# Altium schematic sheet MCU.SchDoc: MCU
size A3; DocumentNumber: MB1165; Revision: C.1; SheetNumber: 2; SheetTotal: 17; Project: STM32469I-EVAL
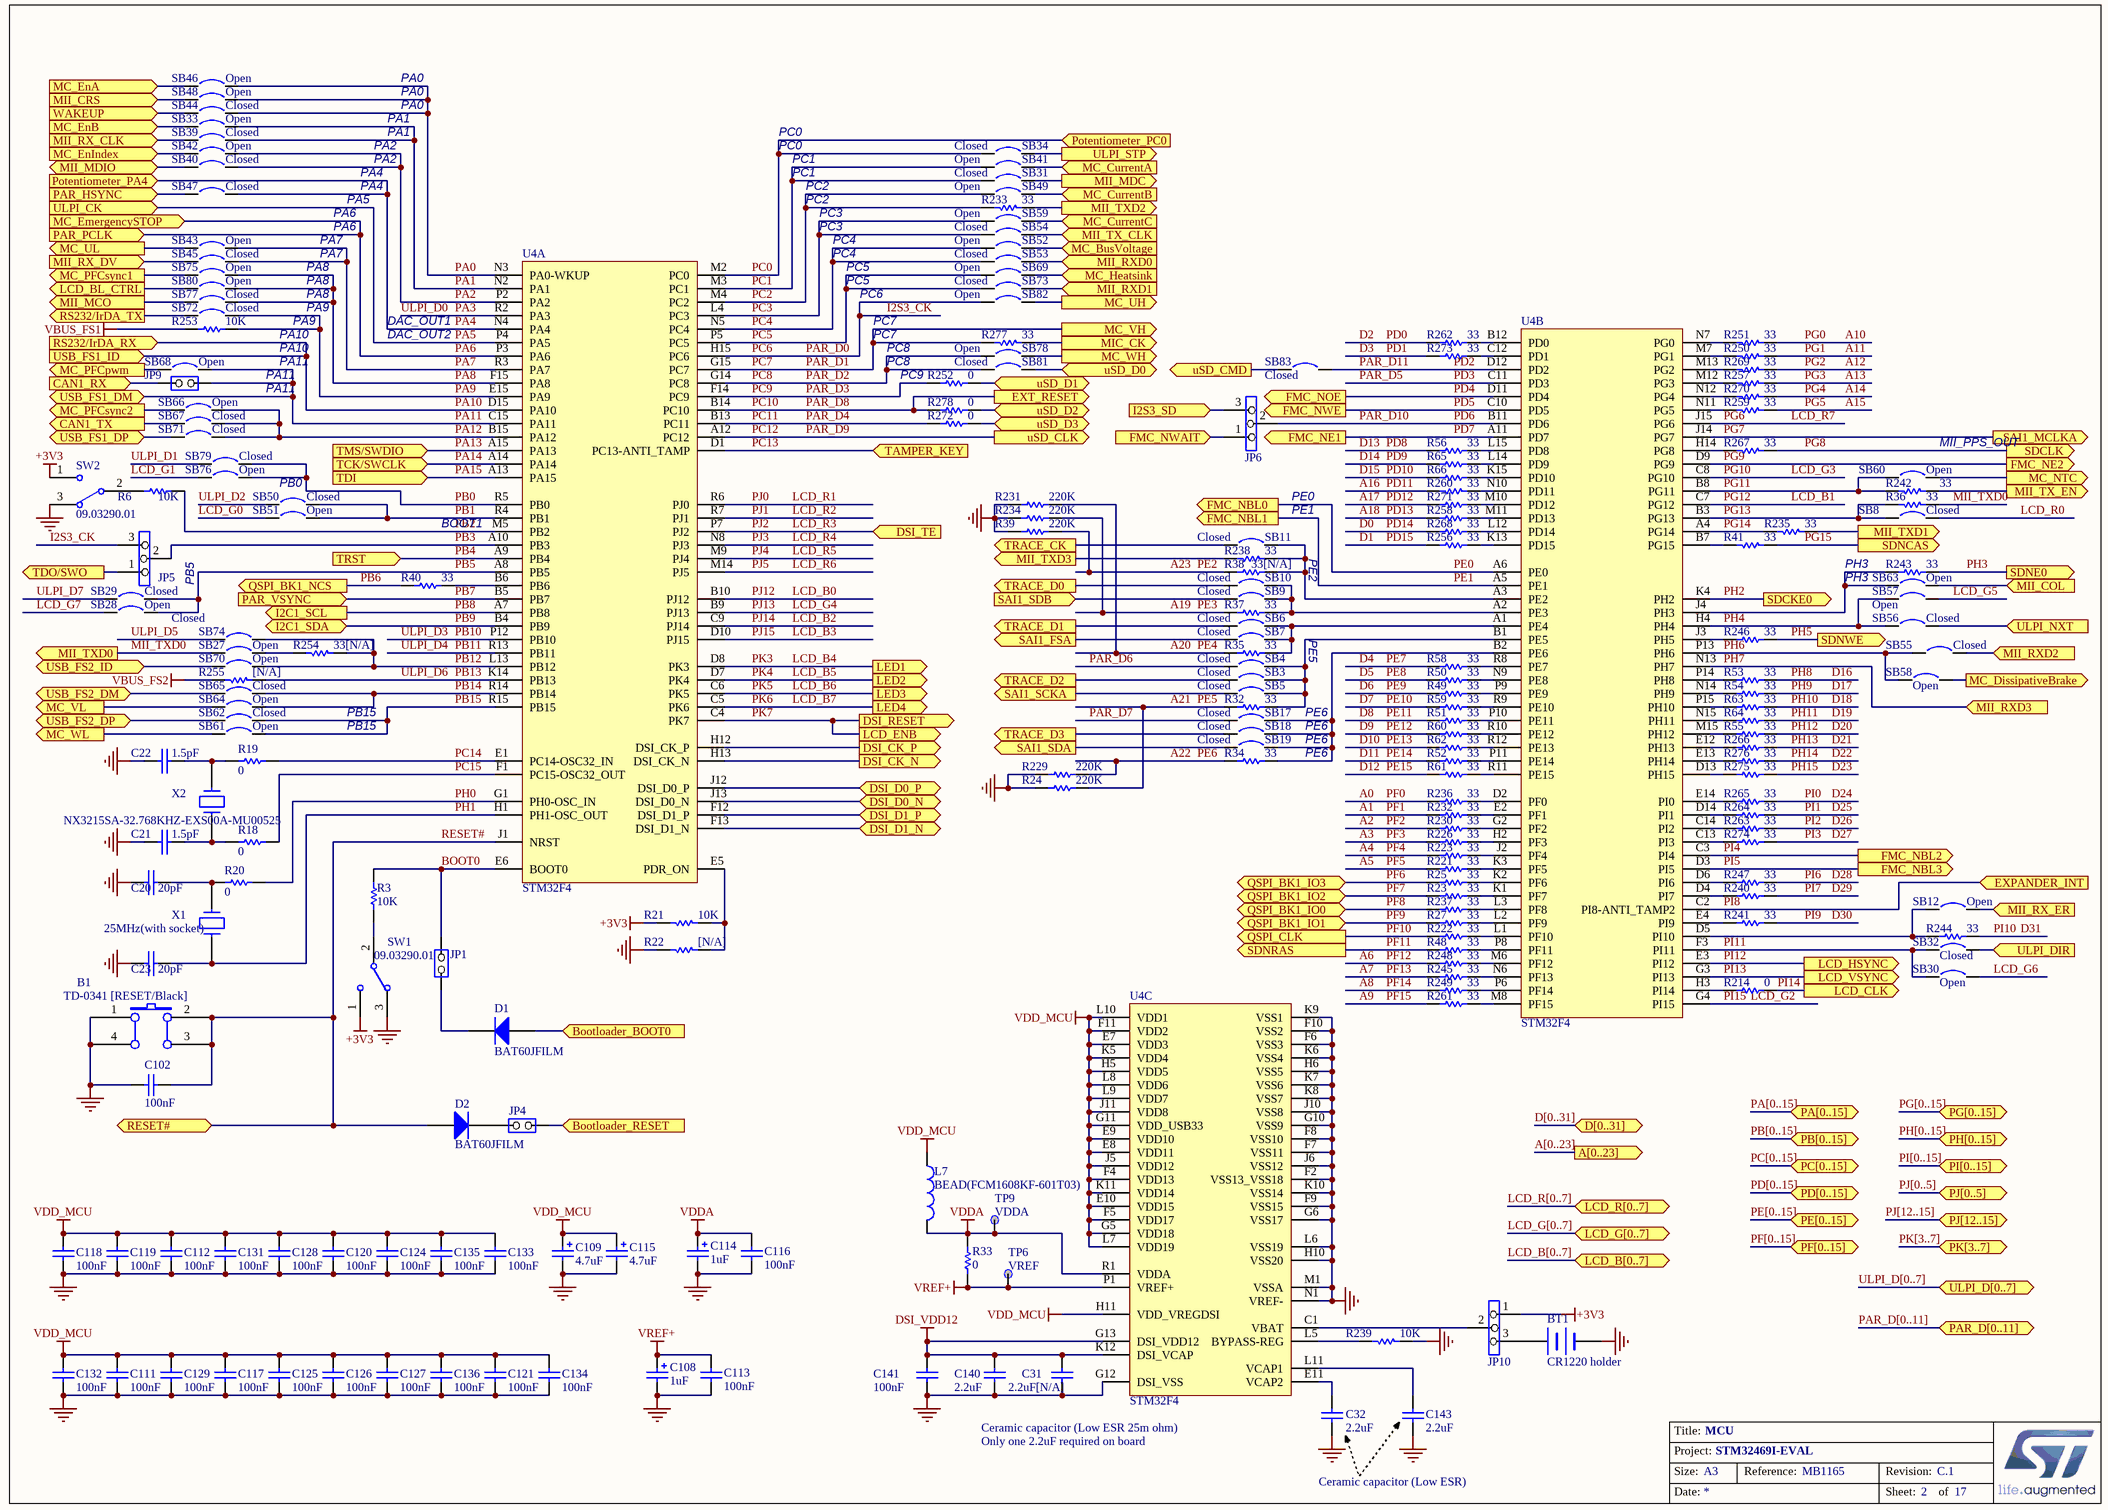
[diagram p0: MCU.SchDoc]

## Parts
B1  TD-0341 [RESET/Black]  [PB10]
BT1  CR1220 holder  [BAT_2SM_CR1220]
C20  20pF  [0603C]
C21  1.5pF  [0603C]
C22  1.5pF  [0603C]
C23  20pF  [0603C]
C31  2.2uF[N/A]  [1206C]
C32  2.2uF  [1206C]
C102  100nF  [0603C]
C108  1uF  [TAN-A]
C109  4.7uF  [TAN-A]
C111  100nF  [0402C]
C112  100nF  [0402C]
C113  100nF  [0402C]
C114  1uF  [TAN-A]
C115  4.7uF  [TAN-A]
C116  100nF  [0402C]
C117  100nF  [0402C]
C118  100nF  [0402C]
C119  100nF  [0402C]
C120  100nF  [0402C]
C121  100nF  [0402C]
C124  100nF  [0402C]
C125  100nF  [0402C]
C126  100nF  [0402C]
C127  100nF  [0402C]
C128  100nF  [0402C]
C129  100nF  [0402C]
C131  100nF  [0402C]
C132  100nF  [0402C]
C133  100nF  [0402C]
C134  100nF  [0402C]
C135  100nF  [0402C]
C136  100nF  [0402C]
C140  2.2uF  [0402C]
C141  100nF  [0402C]
C143  2.2uF  [1206C]
D1  BAT60JFILM  [SOD-323]
D2  BAT60JFILM  [SOD-323]
JP1  (no value)  [SIP2]
JP4  (no value)  [SIP2]
JP5  (no value)  [SIP3]
JP6  (no value)  [SIP3]
JP9  (no value)  [SIP2]
JP10  (no value)  [SIP3]
L7  BEAD(FCM1608KF-601T03)  [0603L]
R3  10K  [0603R]
R6  10K  [0603R]
R18  0  [0603R]
R19  0  [0603R]
R20  0  [0603R]
R21  10K  [0603R]
R22  [N/A]  [0603R]
R23  33  [0402R]
R24  220K  [0603R]
R25  33  [0402R]
R27  33  [0402R]
R32  33  [0402R]
R33  0  [0603R]
R34  33  [0402R]
R35  33  [0402R]
R36  33  [0603R]
R37  33  [0402R]
R38  33[N/A]  [0402R]
R39  220K  [0603R]
R40  33  [0402R]
R41  33  [0402R]
R48  33  [0402R]
R49  33  [0402R]
R50  33  [0402R]
R51  33  [0402R]
R52  33  [0402R]
R53  33  [0402R]
R54  33  [0402R]
R55  33  [0402R]
R56  33  [0402R]
R58  33  [0402R]
R59  33  [0402R]
R60  33  [0402R]
R61  33  [0402R]
R62  33  [0402R]
R63  33  [0402R]
R64  33  [0402R]
R65  33  [0402R]
R66  33  [0402R]
R214  0  [0603R]
R221  33  [0402R]
R222  33  [0402R]
R223  33  [0402R]
R226  33  [0402R]
R229  220K  [0603R]
R230  33  [0402R]
R231  220K  [0603R]
R232  33  [0402R]
R233  33  [0603R]
R234  220K  [0603R]
R235  33  [0603R]
R236  33  [0402R]
R237  33  [0402R]
R238  33  [0603R]
R239  10K  [0603R]
R240  33  [0402R]
R241  33  [0402R]
R242  33  [0603R]
R243  33  [0402R]
R244  33  [0402R]
R245  33  [0402R]
R246  33  [0402R]
R247  33  [0402R]
R248  33  [0402R]
R249  33  [0402R]
R250  33  [0402R]
R251  33  [0402R]
R252  0  [0603R]
R253  10K  [0603R]
R254  33[N/A]  [0603R]
R255  [N/A]  [0603R]
R256  33  [0402R]
R257  33  [0402R]
R258  33  [0402R]
R259  33  [0402R]
R260  33  [0402R]
R261  33  [0402R]
R262  33  [0402R]
R263  33  [0402R]
R264  33  [0402R]
R265  33  [0402R]
R266  33  [0402R]
R267  33  [0402R]
R268  33  [0402R]
R269  33  [0402R]
R270  33  [0402R]
R271  33  [0402R]
R272  0  [0603R]
R273  33  [0402R]
R274  33  [0402R]
R275  33  [0402R]
R276  33  [0402R]
R277  33  [0603R]
R278  0  [0603R]
SB3  Closed  [SB_0603]
SB4  Closed  [SB_0603]
SB5  Closed  [SB_0603]
SB6  Closed  [SB_0603]
SB7  Closed  [SB_0603]
SB8  Closed  [SB_0603]
SB9  Closed  [SB_0603]
SB10  Closed  [SB_0603]
SB11  Closed  [SB_0603]
SB12  Open  [SB_0603]
SB17  Closed  [SB_0603]
SB18  Closed  [SB_0603]
SB19  Closed  [SB_0603]
SB27  Open  [SB_0603]
SB28  Open  [SB_0603]
SB29  Closed  [SB_0603]
SB30  Open  [SB_0603]
SB31  Closed  [SB_0603]
SB32  Closed  [SB_0603]
SB33  Open  [SB_0603]
SB34  Closed  [SB_0603]
SB39  Closed  [SB_0603]
SB40  Closed  [SB_0603]
SB41  Open  [SB_0603]
SB42  Open  [SB_0603]
SB43  Open  [SB_0603]
SB44  Closed  [SB_0603]
SB45  Closed  [SB_0603]
SB46  Open  [SB_0603]
SB47  Closed  [SB_0603]
SB48  Open  [SB_0603]
SB49  Open  [SB_0603]
SB50  Closed  [SB_0603]
SB51  Open  [SB_0603]
SB52  Open  [SB_0603]
SB53  Closed  [SB_0603]
SB54  Closed  [SB_0603]
SB55  Closed  [SB_0603]
SB56  Closed  [SB_0603]
SB57  Open  [SB_0603]
SB58  Open  [SB_0603]
SB59  Open  [SB_0603]
SB60  Open  [SB_0603]
SB61  Open  [SB_0603]
SB62  Closed  [SB_0603]
SB63  Open  [SB_0603]
SB64  Open  [SB_0603]
SB65  Closed  [SB_0603]
SB66  Open  [SB_0603]
SB67  Closed  [SB_0603]
SB68  Open  [SB_0603]
SB69  Open  [SB_0603]
SB70  Open  [SB_0603]
SB71  Closed  [SB_0603]
SB72  Closed  [SB_0603]
SB73  Closed  [SB_0603]
SB74  Closed  [SB_0603]
SB75  Open  [SB_0603]
SB76  Open  [SB_0603]
SB77  Closed  [SB_0603]
SB78  Open  [SB_0603]
SB79  Closed  [SB_0603]
SB80  Open  [SB_0603]
SB81  Closed  [SB_0603]
SB82  Open  [SB_0603]
SB83  Closed  [SB_0603]
SW1  09.03290.01  [SW1_3TH_2R54_10X2R5]
SW2  09.03290.01  [SW1_3TH_2R54_10X2R5]
TP6  VREF  [TP]
TP9  VDDA  [TP]
U4  STM32F4  [BGA216_0R8_13X13_SKT]  (parts A,B,C of 3)
X1  25MHz(with socket)  [XTAL_socket]
X2  NX3215SA-32.768KHZ-EXS00A-MU00525  [XTAL_2SM_3R2X1R5]

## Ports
A[0..23] (out), Bootloader_BOOT0 (in), Bootloader_RESET (in), CAN1_RX (in), CAN1_TX (out), D[0..31] (bidir), DSI_CK_N (out), DSI_CK_P (out), DSI_D0_N (bidir), DSI_D0_P (bidir), DSI_D1_N (bidir), DSI_D1_P (bidir), DSI_RESET (out), DSI_TE (in), EXPANDER_INT (in), EXT_RESET (out), FMC_NBL0 (out), FMC_NBL1 (out), FMC_NBL2 (out), FMC_NBL3 (out), FMC_NE1 (out), FMC_NE2 (out), FMC_NOE (out), FMC_NWAIT (in), FMC_NWE (out), I2C1_SCL (out), I2C1_SDA (bidir), I2S3_SD (in), LCD_B[0..7] (bidir), LCD_BL_CTRL (out), LCD_CLK (out), LCD_ENB (out), LCD_G[0..7] (bidir), LCD_HSYNC (out), LCD_R[0..7] (bidir), LCD_VSYNC (out), LED1 (out), LED2 (out), LED3 (out), LED4 (out), MC_BusVoltage (in), MC_CurrentA (in), MC_CurrentB (in), MC_CurrentC (in), MC_DissipativeBrake (out), MC_EmergencySTOP (in), MC_EnA (in), MC_EnB (in), MC_EnIndex (in), MC_Heatsink (in), MC_NTC (out), MC_PFCpwm (out), MC_PFCsync1 (out), MC_PFCsync2 (out), MC_UH (out), MC_UL (out), MC_VH (out), MC_VL (out), MC_WH (out), MC_WL (out), MIC_CK (out), MII_COL (in), MII_CRS (in), MII_MCO (out), MII_MDC (out), MII_MDIO (bidir), MII_RX_CLK (in), MII_RX_DV (in), MII_RX_ER (in), MII_RXD0 (in), MII_RXD1 (in), MII_RXD2 (in), MII_RXD3 (in), MII_TX_CLK (in), MII_TX_EN (out), MII_TXD0 (out), MII_TXD1 (out), MII_TXD2 (out), MII_TXD3 (out), PA[0..15] (bidir), PAR_D[0..11] (bidir), PAR_HSYNC (in), PAR_PCLK (in), PAR_VSYNC (in), PB[0..15] (bidir), PC[0..15] (bidir), PD[0..15] (bidir), PE[0..15] (bidir), PF[0..15] (bidir), PG[0..15] (bidir), PH[0..15] (bidir), PI[0..15] (bidir), PJ[0..5] (bidir), PJ[12..15] (bidir), PK[3..7] (bidir), Potentiometer_PA4 (in), Potentiometer_PC0 (in), QSPI_BK1_IO0 (bidir), QSPI_BK1_IO1 (bidir), QSPI_BK1_IO2 (bidir), QSPI_BK1_IO3 (bidir), QSPI_BK1_NCS (out), QSPI_CLK (out), RESET# (bidir), RS232/IrDA_RX (in), RS232/IrDA_TX (out), SAI1_FSA (out), SAI1_MCLKA (out), SAI1_SCKA (out), SAI1_SDA (out), SAI1_SDB (in), SDCKE0 (out), SDCLK (out), SDNCAS (out), SDNE0 (out), SDNRAS (out), SDNWE (out), TAMPER_KEY (in), TCK/SWCLK (in), TDI (in), TDO/SWO (out), TMS/SWDIO (in), TRACE_CK (out), TRACE_D0 (out), TRACE_D1 (out), TRACE_D2 (out), TRACE_D3 (out), TRST (in), ULPI_CK (in), ULPI_D[0..7] (bidir), ULPI_DIR (in), ULPI_NXT (in), ULPI_STP (out), USB_FS1_DM (bidir), USB_FS1_DP (bidir), USB_FS1_ID (in), USB_FS2_DM (bidir), USB_FS2_DP (bidir), USB_FS2_ID (bidir), uSD_CLK (out), uSD_CMD (out), uSD_D0 (bidir), uSD_D1 (bidir), uSD_D2 (bidir), uSD_D3 (bidir), WAKEUP (in)

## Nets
+3V3: JP10.1 R21.2 SW1.1 SW2.1
DSI_VDD12: C31.1 C140.1 C141.1 U4.G13(DSI_VDD12) U4.K12(DSI_VCAP)
GND: B1.1(A0) B1.4(A1) BT1.2(-) C20.2 C21.2 C22.2 C23.2 C31.2 C32.2 C102.1 C108.2 C109.2 C111.2 C112.2 C113.1 C114.2 C115.2 C116.1 C117.2 C118.2 C119.2 C120.2 C121.2 C124.2 C125.2 C126.2 C127.2 C128.2 C129.2 C131.2 C132.2 C133.2 C134.2 C135.2 C136.2 C140.2 C141.2 C143.2 R22.2 R24.1 R39.1 R229.1 R231.1 R234.1 R239.1 SW1.3 SW2.3 U4.F2(VSS13_VSS18) U4.F6(VSS3) U4.F7(VSS11) U4.F8(VSS10) U4.F9(VSS15) U4.F10(VSS2) U4.G6(VSS17) U4.G10(VSS9) U4.G12(DSI_VSS) U4.H6(VSS5) U4.H10(VSS20) U4.J6(VSS12) U4.J10(VSS8) U4.K6(VSS4) U4.K7(VSS6) U4.K8(VSS7) U4.K9(VSS1) U4.K10(VSS14) U4.L6(VSS19) U4.M1(VSSA) U4.N1(VREF-)
VBUS_FS1: R253.2
VBUS_FS2: R255.1
VDD_MCU: C109.1 C111.1 C112.1 C115.1 C117.1 C118.1 C119.1 C120.1 C121.1 C124.1 C125.1 C126.1 C127.1 C128.1 C129.1 C131.1 C132.1 C133.1 C134.1 C135.1 C136.1 L7.1 U4.E7(VDD3) U4.E8(VDD11) U4.E9(VDD10) U4.E10(VDD15) U4.F4(VDD13) U4.F5(VDD17) U4.F11(VDD2) U4.G5(VDD18) U4.G11(VDD_USB33) U4.H5(VDD5) U4.H11(VDD_VREGDSI) U4.J5(VDD12) U4.J11(VDD8) U4.K5(VDD4) U4.K11(VDD14) U4.L7(VDD19) U4.L8(VDD6) U4.L9(VDD7) U4.L10(VDD1)
VDDA: C114.1 C116.2 L7.2 R33.1 TP9.1 U4.R1(VDDA)
VREF+: C108.1 C113.2 R33.2 TP6.1 U4.P1(VREF+)
A0: R236.2  [also labelled PF0]
A1: R232.2  [also labelled PF1]
A2: R230.2  [also labelled PF2]
A3: R226.2  [also labelled PF3]
A4: R223.2  [also labelled PF4]
A5: R221.2  [also labelled PF5]
A6: R248.2  [also labelled PF12]
A7: R245.2  [also labelled PF13]
A8: R249.2  [also labelled PF14]
A9: R261.2  [also labelled PF15]
A10: R251.2  [also labelled PG0]
A11: R250.2  [also labelled PG1]
A12: R269.2  [also labelled PG2]
A13: R257.2  [also labelled PG3]
A14: R270.2  [also labelled PG4]
A15: R259.2  [also labelled PG5]
A16: R260.1  [also labelled PD11]
A17: R271.2  [also labelled PD12]
A18: R258.2  [also labelled PD13]
A19: R37.2 R234.2  [also labelled PE3]
A20: R35.2 R231.2  [also labelled PE4]
A21: R24.2 R32.2  [also labelled PE5]
A22: R34.2 R229.2  [also labelled PE6]
A23: R38.2 R39.2  [also labelled PE2]
BOOT0: JP1.2(NO) R3.1 U4.E6(BOOT0)
Bootloader_BOOT0: D1.1(A) ; port Bootloader_BOOT0
Bootloader_RESET: JP4.2(NO) ; port Bootloader_RESET
CAN1_RX: JP9.2(NO) ; port CAN1_RX
CAN1_TX: SB67.1 ; port CAN1_TX
D0: R268.2  [also labelled PD14]
D1: R256.2  [also labelled PD15]
D2: R262.2  [also labelled PD0]
D3: R273.2  [also labelled PD1]
D4: R58.2  [also labelled PE7]
D5: R50.2  [also labelled PE8]
D6: R49.2  [also labelled PE9]
D7: R59.2  [also labelled PE10]
D8: R51.2  [also labelled PE11]
D9: R60.2  [also labelled PE12]
D10: R62.2  [also labelled PE13]
D11: R52.2  [also labelled PE14]
D12: R61.2  [also labelled PE15]
D13: R56.2  [also labelled PD8]
D14: R65.2  [also labelled PD9]
D15: R66.2  [also labelled PD10]
D16: R53.1  [also labelled PH8]
D17: R54.1  [also labelled PH9]
D18: R63.1  [also labelled PH10]
D19: R64.1  [also labelled PH11]
D20: R55.1  [also labelled PH12]
D21: R266.1  [also labelled PH13]
D22: R276.1  [also labelled PH14]
D23: R275.1  [also labelled PH15]
D24: R265.1  [also labelled PI0]
D25: R264.1  [also labelled PI1]
D26: R263.1  [also labelled PI2]
D27: R274.1  [also labelled PI3]
D28: R247.1  [also labelled PI6]
D29: R240.1  [also labelled PI7]
D30: R241.1  [also labelled PI9]
D31: R244.1  [also labelled PI10]
DSI_CK_N: U4.H13(DSI_CK_N) ; port DSI_CK_N
DSI_CK_P: U4.H12(DSI_CK_P) ; port DSI_CK_P
DSI_D0_N: U4.J13(DSI_D0_N) ; port DSI_D0_N
DSI_D0_P: U4.J12(DSI_D0_P) ; port DSI_D0_P
DSI_D1_N: U4.F13(DSI_D1_N) ; port DSI_D1_N
DSI_D1_P: U4.F12(DSI_D1_P) ; port DSI_D1_P
FMC_NWAIT: JP6.1 ; port FMC_NWAIT
I2S3_CK: JP5.3 SB82.1 U4.H15(PC6)  [also labelled PAR_D0, PC6]
I2S3_SD: JP6.3 ; port I2S3_SD
LCD_B0: U4.B10(PJ12)  [also labelled PJ12]
LCD_B1: U4.C7(PG12)  [also labelled PG12]
LCD_B2: U4.C9(PJ14)  [also labelled PJ14]
LCD_B3: U4.D10(PJ15)  [also labelled PJ15]
LCD_B4: U4.D8(PK3) ; port LED1  [also labelled PK3]
LCD_B5: U4.D7(PK4) ; port LED2  [also labelled PK4]
LCD_B6: U4.C6(PK5) ; port LED3  [also labelled PK5]
LCD_B7: U4.C5(PK6) ; port LED4  [also labelled PK6]
LCD_BL_CTRL: SB80.1 ; port LCD_BL_CTRL
LCD_G0: SB51.1
LCD_G1: SB76.1
LCD_G2: U4.G4(PI15)  [also labelled PI15]
LCD_G3: U4.C8(PG10)  [also labelled PG10]
LCD_G4: U4.B9(PJ13)  [also labelled PJ13]
LCD_G5: SB57.2
LCD_G6: SB30.2
LCD_G7: SB28.1
LCD_R0: SB8.2
LCD_R1: U4.R6(PJ0)  [also labelled PJ0]
LCD_R2: U4.R7(PJ1)  [also labelled PJ1]
LCD_R3: U4.P7(PJ2) ; port DSI_TE  [also labelled PJ2]
LCD_R4: U4.N8(PJ3)  [also labelled PJ3]
LCD_R5: U4.M9(PJ4)  [also labelled PJ4]
LCD_R6: U4.M14(PJ5)  [also labelled PJ5]
LCD_R7: U4.J15(PG6)  [also labelled PG6]
MC_BusVoltage: SB52.2 ; port MC_BusVoltage
MC_CurrentA: SB41.2 ; port MC_CurrentA
MC_CurrentB: SB49.2 ; port MC_CurrentB
MC_CurrentC: SB59.2 ; port MC_CurrentC
MC_DissipativeBrake: SB58.2 ; port MC_DissipativeBrake
MC_EnA: SB46.1 ; port MC_EnA
MC_EnB: SB33.1 ; port MC_EnB
MC_EnIndex: SB42.1 ; port MC_EnIndex
MC_Heatsink: SB69.2 ; port MC_Heatsink
MC_NTC: SB60.2 ; port MC_NTC
MC_PFCpwm: SB68.1 ; port MC_PFCpwm
MC_PFCsync1: SB75.1 ; port MC_PFCsync1
MC_PFCsync2: SB66.1 ; port MC_PFCsync2
MC_UH: SB82.2 ; port MC_UH
MC_UL: SB43.1 ; port MC_UL
MC_VL: SB64.1 ; port MC_VL
MC_WH: SB78.2 ; port MC_WH
MC_WL: SB61.1 ; port MC_WL
MIC_CK: R277.2 ; port MIC_CK
MII_COL: SB63.2 ; port MII_COL
MII_CRS: SB48.1 ; port MII_CRS
MII_MCO: SB77.1 ; port MII_MCO
MII_MDC: SB31.2 ; port MII_MDC
MII_MDIO: SB40.1 ; port MII_MDIO
MII_RX_CLK: SB39.1 ; port MII_RX_CLK
MII_RX_DV: SB45.1 ; port MII_RX_DV
MII_RX_ER: SB12.2 ; port MII_RX_ER
MII_RXD0: SB53.2 ; port MII_RXD0
MII_RXD1: SB73.2 ; port MII_RXD1
MII_RXD2: SB55.2 ; port MII_RXD2
MII_TX_CLK: SB54.2 ; port MII_TX_CLK
MII_TX_EN: R242.2 ; port MII_TX_EN
MII_TXD0: R36.2 SB27.1 ; port MII_TXD0
MII_TXD1: R235.2 ; port MII_TXD1
MII_TXD2: R233.2 ; port MII_TXD2
MII_TXD3: R238.1 ; port MII_TXD3
PA0: SB44.2 SB46.2 SB48.2 U4.N3(PA0-WKUP)
PA1: SB33.2 SB39.2 U4.N2(PA1)
PA2: SB40.2 SB42.2 U4.P2(PA2)
PA3: U4.R2(PA3)  [also labelled ULPI_D0]
PA4: SB47.2 U4.N4(PA4) ; port Potentiometer_PA4
PA5: U4.P4(PA5) ; port ULPI_CK
PA6: U4.P3(PA6) ; port MC_EmergencySTOP, port PAR_PCLK
PA7: SB43.2 SB45.2 U4.R3(PA7)
PA8: SB75.2 SB77.2 SB80.2 U4.F15(PA8)
PA9: R253.1 SB72.2 U4.E15(PA9)
PA10: U4.D15(PA10) ; port RS232/IrDA_RX, port USB_FS1_ID
PA11: JP9.1(COMMON) SB68.2 U4.C15(PA11) ; port USB_FS1_DM
PA12: SB66.2 SB67.2 SB71.2 U4.B15(PA12)
PA13: U4.A15(PA13) ; port TMS/SWDIO
PA14: U4.A14(PA14) ; port TCK/SWCLK
PA15: U4.A13(PA15) ; port TDI
PAR_D1: R277.1 U4.G15(PC7) ; port MC_VH  [also labelled PC7]
PAR_D2: SB78.1 SB81.1 U4.G14(PC8)  [also labelled PC8]
PAR_D3: R252.2 U4.F14(PC9)  [also labelled PC9]
PAR_D4: R272.2 U4.B13(PC11)  [also labelled PC11]
PAR_D5: U4.C11(PD3)  [also labelled PD3]
PAR_D6: SB4.1
PAR_D7: SB17.1
PAR_D8: R278.2 U4.B14(PC10) ; port EXT_RESET  [also labelled PC10]
PAR_D9: U4.A12(PC12) ; port uSD_CLK  [also labelled PC12]
PAR_D10: JP6.2 U4.B11(PD6)  [also labelled PD6]
PAR_D11: SB83.2 U4.D12(PD2)  [also labelled PD2]
PAR_HSYNC: SB47.1 ; port PAR_HSYNC
PB0: SB76.2 SB79.2 U4.R5(PB0)
PB1: SB50.2 SB51.2 U4.R4(PB1)
PB2: R6.2 U4.M5(PB2)
PB3: JP5.2 U4.A10(PB3)
PB4: U4.A9(PB4) ; port TRST
PB5: SB28.2 SB29.2 U4.A8(PB5)
PB6: R40.2 ; port QSPI_BK1_NCS
PB7: U4.B5(PB7) ; port PAR_VSYNC
PB8: U4.A7(PB8) ; port I2C1_SCL
PB9: U4.B4(PB9) ; port I2C1_SDA
PB10: U4.P12(PB10)  [also labelled ULPI_D3]
PB11: U4.R13(PB11)  [also labelled ULPI_D4]
PB12: R254.2 SB70.2 SB74.2 U4.L13(PB12)
PB13: R255.2 U4.K14(PB13)  [also labelled ULPI_D6]
PB14: SB64.2 SB65.2 U4.R14(PB14)
PB15: SB61.2 SB62.2 U4.R15(PB15)
PC0: SB34.1 U4.M2(PC0) ; port Potentiometer_PC0
PC1: SB31.1 SB41.1 U4.M3(PC1)
PC2: R233.1 SB49.1 U4.M4(PC2)
PC3: SB54.1 SB59.1 U4.L4(PC3)
PC4: SB52.1 SB53.1 U4.N5(PC4)
PC5: SB69.1 SB73.1 U4.P5(PC5)
PC13: U4.D1(PC13-ANTI_TAMP) ; port TAMPER_KEY
PC14: R19.2 U4.E1(PC14-OSC32_IN)
PC15: R18.2 U4.F1(PC15-OSC32_OUT)
PD4: U4.D11(PD4) ; port FMC_NOE
PD5: U4.C10(PD5) ; port FMC_NWE
PD7: U4.A11(PD7) ; port FMC_NE1
PE0: U4.A6(PE0) ; port FMC_NBL0
PE1: U4.A5(PE1) ; port FMC_NBL1
PF6: R25.2 ; port QSPI_BK1_IO3
PF7: R23.2 ; port QSPI_BK1_IO2
PF8: R237.2 ; port QSPI_BK1_IO0
PF9: R27.2 ; port QSPI_BK1_IO1
PF10: R222.2 ; port QSPI_CLK
PF11: R48.2 ; port SDNRAS
PG7: U4.J14(PG7) ; port SAI1_MCLKA
PG8: R267.2 ; port SDCLK
PG9: U4.D9(PG9) ; port FMC_NE2
PG11: R242.1 SB60.1 U4.B8(PG11)
PG13: R36.1 SB8.1 U4.B3(PG13)
PG14: R235.1 U4.A4(PG14)
PG15: R41.2 ; port SDNCAS
PH0: R20.1 U4.G1(PH0-OSC_IN)
PH1: C23.1 U4.H1(PH1-OSC_OUT) X1.1
PH2: U4.K4(PH2) ; port SDCKE0
PH3: R243.1 ; port SDNE0
PH4: SB56.1 SB57.1 U4.H4(PH4)
PH5: R246.1 ; port SDNWE
PH6: SB55.1 SB58.1 U4.P13(PH6)
PH7: U4.N13(PH7) ; port MII_RXD3
PI4: U4.C3(PI4) ; port FMC_NBL2
PI5: U4.D3(PI5) ; port FMC_NBL3
PI8: U4.C2(PI8-ANTI_TAMP2) ; port EXPANDER_INT
PI11: SB30.1 SB32.1 U4.F3(PI11)
PI12: U4.E3(PI12) ; port LCD_HSYNC
PI13: U4.G3(PI13) ; port LCD_VSYNC
PI14: R214.1 ; port LCD_CLK
PK7: U4.C4(PK7) ; port LCD_ENB, port DSI_RESET
RESET#: B1.2(B0) B1.3(B1) C102.2 D2.1(A) U4.J1(NRST) ; port RESET#
RS232/IrDA_TX: SB72.1 ; port RS232/IrDA_TX
SAI1_FSA: SB7.1 ; port SAI1_FSA
SAI1_SCKA: SB5.1 ; port SAI1_SCKA
SAI1_SDA: SB19.1 ; port SAI1_SDA
SAI1_SDB: SB9.1 ; port SAI1_SDB
TDO/SWO: JP5.1 ; port TDO/SWO
TRACE_CK: SB11.1 ; port TRACE_CK
TRACE_D0: SB10.1 ; port TRACE_D0
TRACE_D1: SB6.1 ; port TRACE_D1
TRACE_D2: SB3.1 ; port TRACE_D2
TRACE_D3: SB18.1 ; port TRACE_D3
ULPI_D1: SB79.1
ULPI_D2: SB50.1
ULPI_D5: SB74.1
ULPI_D7: SB29.1
ULPI_DIR: SB32.2 ; port ULPI_DIR
ULPI_NXT: SB56.2 ; port ULPI_NXT
ULPI_STP: SB34.2 ; port ULPI_STP
USB_FS1_DP: SB71.1 ; port USB_FS1_DP
USB_FS2_DM: SB65.1 ; port USB_FS2_DM
USB_FS2_DP: SB62.1 ; port USB_FS2_DP
USB_FS2_ID: SB70.1 ; port USB_FS2_ID
uSD_CMD: SB83.1 ; port uSD_CMD
uSD_D0: SB81.2 ; port uSD_D0
uSD_D1: R252.1 ; port uSD_D1
uSD_D2: R278.1 ; port uSD_D2
uSD_D3: R272.1 ; port uSD_D3
WAKEUP: SB44.1 ; port WAKEUP
NetBT1_1: BT1.1(+) JP10.3
NetC20_1: C20.1 R20.2 X1.2
NetC21_1: C21.1 R18.1 X2.1
NetC22_1: C22.1 R19.1 X2.2
NetC32_1: C32.1 U4.E11(VCAP2)
NetC143_1: C143.1 U4.L11(VCAP1)
NetD1_2: D1.2(K) JP1.1(COMMON)
NetD2_2: D2.2(K) JP4.1(COMMON)
NetJP10_2: JP10.2 U4.C1(VBAT)
NetR3_2: R3.2 SW1.2
NetR6_1: R6.1 SW2.2
NetR21_1: R21.1 R22.1 U4.E5(PDR_ON)
NetR23_1: R23.1 U4.K1(PF7)
NetR25_1: R25.1 U4.K2(PF6)
NetR27_1: R27.1 U4.L2(PF9)
NetR32_1: R32.1 SB3.2 SB4.2 SB5.2 U4.B1(PE5)
NetR34_1: R34.1 SB17.2 SB18.2 SB19.2 U4.B2(PE6)
NetR35_1: R35.1 SB6.2 SB7.2 U4.A1(PE4)
NetR37_1: R37.1 SB9.2 SB10.2 U4.A2(PE3)
NetR38_1: R38.1 R238.2 SB11.2 U4.A3(PE2)
NetR40_1: R40.1 U4.B6(PB6)
NetR41_1: R41.1 U4.B7(PG15)
NetR48_1: R48.1 U4.P8(PF11)
NetR49_1: R49.1 U4.P9(PE9)
NetR50_1: R50.1 U4.N9(PE8)
NetR51_1: R51.1 U4.P10(PE11)
NetR52_1: R52.1 U4.P11(PE14)
NetR53_2: R53.2 U4.P14(PH8)
NetR54_2: R54.2 U4.N14(PH9)
NetR55_2: R55.2 U4.M15(PH12)
NetR56_1: R56.1 U4.L15(PD8)
NetR58_1: R58.1 U4.R8(PE7)
NetR59_1: R59.1 U4.R9(PE10)
NetR60_1: R60.1 U4.R10(PE12)
NetR61_1: R61.1 U4.R11(PE15)
NetR62_1: R62.1 U4.R12(PE13)
NetR63_2: R63.2 U4.P15(PH10)
NetR64_2: R64.2 U4.N15(PH11)
NetR65_1: R65.1 U4.L14(PD9)
NetR66_1: R66.1 U4.K15(PD10)
NetR214_2: R214.2 U4.H3(PI14)
NetR221_1: R221.1 U4.K3(PF5)
NetR222_1: R222.1 U4.L1(PF10)
NetR223_1: R223.1 U4.J2(PF4)
NetR226_1: R226.1 U4.H2(PF3)
NetR230_1: R230.1 U4.G2(PF2)
NetR232_1: R232.1 U4.E2(PF1)
NetR236_1: R236.1 U4.D2(PF0)
NetR237_1: R237.1 U4.L3(PF8)
NetR239_2: R239.2 U4.L5(BYPASS-REG)
NetR240_2: R240.2 U4.D4(PI7)
NetR241_2: R241.2 U4.E4(PI9)
NetR243_2: R243.2 SB63.1 U4.J4(PH3)
NetR244_2: R244.2 SB12.1 U4.D5(PI10)
NetR245_1: R245.1 U4.N6(PF13)
NetR246_2: R246.2 U4.J3(PH5)
NetR247_2: R247.2 U4.D6(PI6)
NetR248_1: R248.1 U4.M6(PF12)
NetR249_1: R249.1 U4.P6(PF14)
NetR250_1: R250.1 U4.M7(PG1)
NetR251_1: R251.1 U4.N7(PG0)
NetR254_1: R254.1 SB27.2
NetR256_1: R256.1 U4.K13(PD15)
NetR257_1: R257.1 U4.M12(PG3)
NetR258_1: R258.1 U4.M11(PD13)
NetR259_1: R259.1 U4.N11(PG5)
NetR260_2: R260.2 U4.N10(PD11)
NetR261_1: R261.1 U4.M8(PF15)
NetR262_1: R262.1 U4.B12(PD0)
NetR263_2: R263.2 U4.C14(PI2)
NetR264_2: R264.2 U4.D14(PI1)
NetR265_2: R265.2 U4.E14(PI0)
NetR266_2: R266.2 U4.E12(PH13)
NetR267_1: R267.1 U4.H14(PG8)
NetR268_1: R268.1 U4.L12(PD14)
NetR269_1: R269.1 U4.M13(PG2)
NetR270_1: R270.1 U4.N12(PG4)
NetR271_1: R271.1 U4.M10(PD12)
NetR273_1: R273.1 U4.C12(PD1)
NetR274_2: R274.2 U4.C13(PI3)
NetR275_2: R275.2 U4.D13(PH15)
NetR276_2: R276.2 U4.E13(PH14)

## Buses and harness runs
bus A[0..23] = port A[0..23]
bus D[0..31] = port D[0..31]
bus LCD_B[0..7] = port LCD_B[0..7]
bus LCD_G[0..7] = port LCD_G[0..7]
bus LCD_R[0..7] = port LCD_R[0..7]
bus PA[0..15] = port PA[0..15]
bus PAR_D[0..11] = port PAR_D[0..11]
bus PB[0..15] = port PB[0..15]
bus PC[0..15] = port PC[0..15]
bus PD[0..15] = port PD[0..15]
bus PE[0..15] = port PE[0..15]
bus PF[0..15] = port PF[0..15]
bus PG[0..15] = port PG[0..15]
bus PH[0..15] = port PH[0..15]
bus PI[0..15] = port PI[0..15]
bus PJ[0..5] = port PJ[0..5]
bus PJ[12..15] = port PJ[12..15]
bus PK[3..7] = port PK[3..7]
bus ULPI_D[0..7] = port ULPI_D[0..7]

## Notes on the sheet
- PA0
- PA4
- PA2
- PA1
- PC0
- PC1
- PA7
- PA6
- PA5
- PC2
- PC3
- PC4
- PA8
- PA9
- PC5
- PC6
- PA11
- PA10
- DAC_OUT1
- DAC_OUT2
- PC7
- PC8
- PC9
- MII_PPS_OUT
- (near SB50) PB0
- PE0
- PE1
- PB5
- BOOT1
- PE2
- PH3
- PE5
- PB15
- PE6
- Ceramic capacitor (Low ESR 25m ohm)
- Only one 2.2uF required on board
- Ceramic capacitor (Low ESR)

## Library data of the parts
B1 = SW PUSHBUTTON: SE PUSHBUTTON
BT1 = BATTERY
C20-C23 C111 C112 C117-C121 C124-C129 C131-C136 C141 = CAP: Capacitor
C31 C32 C113 C116 C143 = Cap: Capacitor; Value: 10nF
C102 = CAP: Capacitor; Value: 100pF
C108 C114 = Cap Pol1: Polarized Capacitor (Radial); Value: 10uF
C109 C115 = Cap Pol1: Polarized Capacitor (Radial); Value: 47uF
C140 = CAP: Capacitor; Value: 100nF
D1 D2 = Diode: Default Diode; Code - JEDEC: DO-214-AB
JP1 JP4 JP9 = JP2
JP5 JP6 JP10 = Jumper3
L7 = Inductor: Value: 100uH
R3 R24 R39 R229 R231 R234 R253 = res1: Resistor; Value: 1K
R6 R18-R23 R25 R27 R32-R38 R40 R41 R48-R56 R58-R66 R214 R221-R223 R226 R230 R232 R233 R235-R252 R254-R278 = Res1: Resistor; Value: 1K
SB3-SB11 SB17-SB19 SB29 SB31 SB32 SB34 SB39 SB40 SB44 SB45 SB47 SB50 SB53-SB56 SB62 SB65 SB67 SB71-SB74 SB77 SB79 SB81 SB83 = Circuit Breaker_close: Circuit Breaker
SB12 SB27 SB28 SB30 SB33 SB41-SB43 SB46 SB48 SB49 SB51 SB52 SB57-SB61 SB63 SB64 SB66 SB68-SB70 SB75 SB76 SB78 SB80 SB82 = Circuit Breaker
SW1 SW2 = SW-SPDT: SPDT Subminiature Toggle Switch, Right Angle Mounting, Vertical Actuation; Revision 1: Jul-2002: Re-released for DXP Platform.; Revision 2: 17-Dec-2003: Schematic revised, PCB Footprint replaced.
TP6 TP9 = TP
U4 = Manta_Dragon_TFBGA216
X1 = CRYSTAL
X2 = CRYSTAL_32K: Crystal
